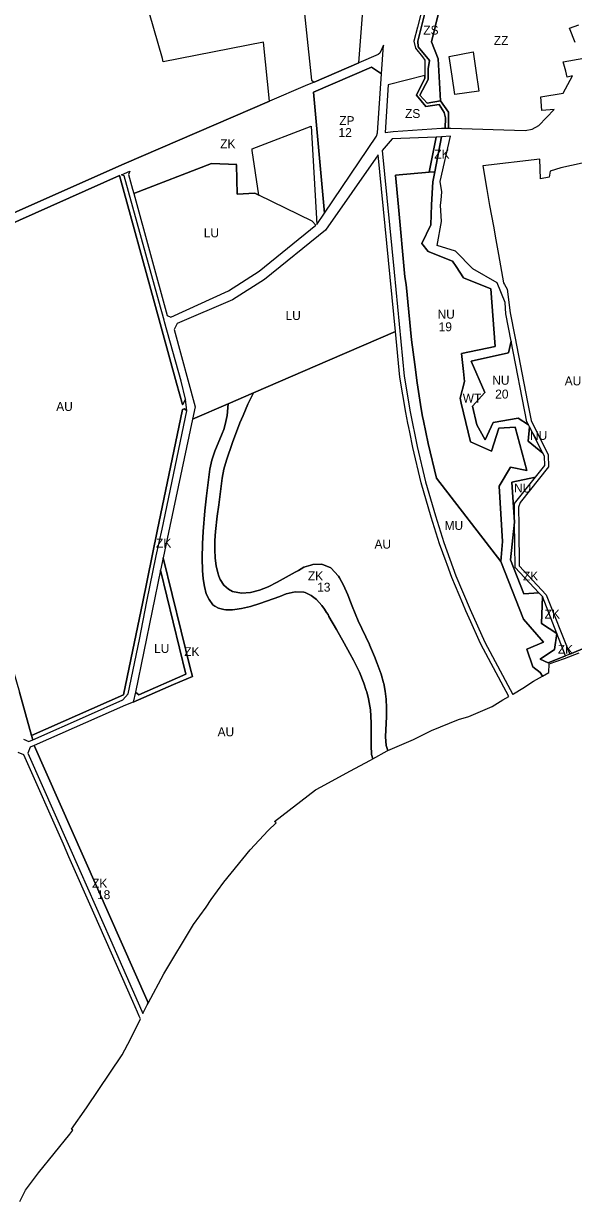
# Model space of a CAD drawing. Extents: x -522079 to -518833, y -1142398 to -1139961.
# Drawn here: x -521003 to -520386, y -1142382 to -1141061 of the extents above; entities that cross this region are included whole.
import ezdxf

# ---------------------------------------------------------------- set-up
doc = ezdxf.new("R2010")
doc.units = 0
for name, color, linetype in [('90640013', 7, 'Continuous'), ('90660013', 7, 'Continuous'), ('90670013', 7, 'Continuous'), ('90680023', 7, 'Continuous'), ('90710013', 7, 'Continuous'), ('90710023', 7, 'Continuous'), ('90730013', 7, 'Continuous'), ('90730023', 7, 'Continuous'), ('90750013', 7, 'Continuous'), ('90770013', 7, 'Continuous'), ('90830013', 7, 'Continuous'), ('ID_navrh', 7, 'Continuous')]:
    doc.layers.add(name, color=color, linetype=linetype)

msp = doc.modelspace()

# ---------------------------------------------------------------- linework, layer by layer
at = {"layer": '90640013'}
for points in [[(-520556.5, -1141046.1), (-520561.24, -1141065.24), (-520565.18, -1141081.15), (-520563.4, -1141088.78), (-520555.74, -1141098.46), (-520552.84, -1141102.13), (-520552.98, -1141119.42), (-520553, -1141122.43), (-520562.26, -1141141.67), (-520551.87, -1141154.33), (-520536.94, -1141152.14), (-520531.44, -1141160.96), (-520529.73, -1141167.05), (-520530.26, -1141178.39), (-520526.48, -1141178.44), (-520526.38, -1141166.45), (-520526.34, -1141160.53), (-520535.5, -1141147.72), (-520550.27, -1141150.4), (-520558.62, -1141141.55), (-520549.21, -1141123.97), (-520549.23, -1141120.44), (-520549.29, -1141112.12), (-520547.68, -1141102.49), (-520560.53, -1141087.18), (-520560.89, -1141080.93), (-520556.84, -1141064.48), (-520552.06, -1141045.13)], [(-520276.36, -1141720.39), (-520390.37, -1141768.15), (-520395.26, -1141770.17), (-520414.86, -1141777.92), (-520423.68, -1141774.01), (-520407.65, -1141762.99), (-520405.02, -1141744.98), (-520422.16, -1141733.79), (-520421.11, -1141703.69), (-520425.12, -1141699.44), (-520442.1, -1141700.42), (-520456.84, -1141662.39), (-520452.43, -1141620.06), (-520455.53, -1141575.25), (-520428.95, -1141569.87), (-520418.4, -1141556.83), (-520419, -1141546.21), (-520420.69, -1141542.88), (-520437.33, -1141529.38), (-520435.68, -1141513.27), (-520436.83, -1141511), (-520448.25, -1141503.52), (-520476.51, -1141508.33), (-520485.33, -1141527.78), (-520494.54, -1141511.04), (-520499.43, -1141490.33), (-520485.81, -1141474.99), (-520501.13, -1141439.65), (-520459.35, -1141430.33), (-520456.11, -1141417.28), (-520462.06, -1141386.7), (-520463.1, -1141373.93), (-520471.76, -1141351.9), (-520499.06, -1141336.21), (-520518.61, -1141316.36), (-520539.2, -1141310.09), (-520534.35, -1141283.17), (-520535.3, -1141264.93), (-520534.84, -1141259.42), (-520534.05, -1141249.88), (-520535.7, -1141238.47), (-520524.27, -1141187.6), (-520534.17, -1141188.18), (-520541.94, -1141227.47), (-520544.19, -1141238.83), (-520545.37, -1141264.63), (-520546.39, -1141287.04), (-520556.25, -1141307.68), (-520549.32, -1141316.76), (-520521.95, -1141327.46), (-520517.94, -1141333.55), (-520509.58, -1141346.13), (-520479.06, -1141358.55), (-520474.23, -1141423.42), (-520512.06, -1141431.3), (-520509.69, -1141451.35), (-520508.38, -1141462.38), (-520513.39, -1141481.08), (-520512.09, -1141486.67), (-520501.99, -1141530.25), (-520478.09, -1141540.57), (-520469.99, -1141514.94), (-520451.9, -1141513.8), (-520438.57, -1141562.32), (-520457.06, -1141558.71), (-520469.63, -1141579.9), (-520465.85, -1141641.84), (-520467.83, -1141664.2), (-520442.29, -1141729.04), (-520420.15, -1141754.6), (-520438.59, -1141762.62), (-520431.99, -1141782.5), (-520423.68, -1141788.92), (-520421.03, -1141792.82), (-520413.91, -1141788.74), (-520413.8, -1141779.11), (-520396.49, -1141772.96), (-520379.93, -1141766.64)]]:
    msp.add_lwpolyline(points, dxfattribs=at)
at = {"layer": '90660013'}
msp.add_lwpolyline([(-520552.06, -1141045.13), (-520556.84, -1141064.48), (-520560.89, -1141080.93), (-520560.53, -1141087.18), (-520547.68, -1141102.49), (-520549.29, -1141112.12), (-520549.23, -1141120.44), (-520549.21, -1141123.97), (-520558.62, -1141141.55), (-520550.27, -1141150.4), (-520535.5, -1141147.72), (-520538.13, -1141100.63), (-520545.68, -1141081.75), (-520537, -1141046.7)], dxfattribs=at)
msp.add_lwpolyline([(-520530.26, -1141178.39), (-520529.73, -1141167.05), (-520531.44, -1141160.96), (-520536.94, -1141152.14), (-520551.87, -1141154.33), (-520562.26, -1141141.67), (-520553, -1141122.43), (-520552.98, -1141119.42), (-520594.25, -1141129.86), (-520597.46, -1141183.55), (-520588.63, -1141182.42), (-520534.49, -1141178.34)], close=True, dxfattribs=at)
at = {"layer": '90670013'}
for points in [[(-520537, -1141046.7), (-520545.68, -1141081.75), (-520538.13, -1141100.63), (-520535.5, -1141147.72), (-520526.34, -1141160.53), (-520526.38, -1141166.45), (-520526.48, -1141178.44), (-520523.78, -1141178.47), (-520440.68, -1141181.04), (-520432.59, -1141179.7), (-520425.27, -1141175.41), (-520408.18, -1141157.48), (-520421.91, -1141158.52), (-520423.06, -1141143.4), (-520397.97, -1141139.24), (-520387.46, -1141120.02), (-520393.3, -1141121.36), (-520395.09, -1141114.42), (-520397.79, -1141103.97), (-520374.68, -1141099.98)], [(-520384.48, -1141082.4), (-520390.79, -1141066.51), (-520380.42, -1141062.83)], [(-520498.69, -1141092.95), (-520495.67, -1141113.78), (-520492.31, -1141136.96), (-520519.42, -1141140.9), (-520522.42, -1141120.25), (-520525.62, -1141098.2), (-520498.69, -1141092.95)]]:
    msp.add_lwpolyline(points, dxfattribs=at)
at = {"layer": '90680023'}
msp.add_lwpolyline([(-520601.54, -1141117.64), (-520612.8, -1141110.04), (-520677.78, -1141138.02), (-520665.65, -1141273.94), (-520607.02, -1141187.64), (-520606.07, -1141183.78)], close=True, dxfattribs=at)
at = {"layer": '90710013'}
msp.add_lwpolyline([(-521140.66, -1141340.91), (-520895.18, -1141231.65), (-520856.02, -1141374.46), (-520831.3, -1141464.59), (-520824.77, -1141488.43), (-520824.28, -1141488.21), (-520821.3, -1141482.16), (-520826.14, -1141462.3), (-520844.73, -1141395.54), (-520845.27, -1141393.64), (-520851.22, -1141372.34), (-520889.86, -1141232.13), (-520893.13, -1141230.74), (-520883.56, -1141226.59), (-520885.33, -1141230.38), (-520880.53, -1141246.97), (-520879.25, -1141251.61), (-520792.12, -1141217.97), (-520763.86, -1141219.18), (-520764.2, -1141219.7), (-520763.26, -1141252.34), (-520743.39, -1141251.48), (-520739.03, -1141253.62), (-520746.38, -1141203.48), (-520746.65, -1141201.66), (-520680.34, -1141176.38), (-520674.18, -1141286.49), (-520665.65, -1141273.94), (-520677.78, -1141138.02), (-520612.8, -1141110.04), (-520601.54, -1141117.64), (-520599.33, -1141085.41), (-520603.47, -1141094.45), (-520605.48, -1141096), (-520627.13, -1141105.32), (-520676.95, -1141126.77), (-520686.99, -1141131.09), (-520727.16, -1141148.38), (-520890.16, -1141218.54), (-520895.96, -1141221.04), (-521038.45, -1141284.46)], dxfattribs=at)
for points in [[(-520540.34, -1141188.43), (-520548.16, -1141227.97), (-520541.94, -1141227.47), (-520534.17, -1141188.18)], [(-520993.82, -1141859.25), (-520992.44, -1141864.11), (-520930.02, -1141836.55), (-520891.63, -1141819.53), (-520885.53, -1141812.75), (-520873.01, -1141751.95), (-520864.49, -1141709.14), (-520854, -1141657.98), (-520847.36, -1141628.04), (-520819.82, -1141495.44), (-520822.47, -1141493.04), (-520824.63, -1141494.01), (-520852.89, -1141630.48), (-520869.65, -1141711.4), (-520878.55, -1141754.38), (-520890.85, -1141813.79)], [(-520425.12, -1141699.44), (-520451.86, -1141671.07), (-520452.43, -1141620.06), (-520456.84, -1141662.39), (-520442.1, -1141700.42)], [(-520877.47, -1141810.66), (-520879.93, -1141822.22), (-520834.71, -1141802.36), (-520813.61, -1141793.09), (-520815.91, -1141783.74), (-520846.32, -1141660.34), (-520849.15, -1141674.02), (-520820.88, -1141790.77), (-520873.57, -1141813.91)], [(-520421.11, -1141703.69), (-520422.16, -1141733.79), (-520405.02, -1141744.98)], [(-520395.26, -1141770.17), (-520405.02, -1141744.98), (-520407.65, -1141762.99), (-520423.68, -1141774.01), (-520414.86, -1141777.92)]]:
    msp.add_lwpolyline(points, close=True, dxfattribs=at)
at = {"layer": '90710023'}
for points in [[(-520594.48, -1141876.16), (-520596.28, -1141870.76), (-520596.94, -1141860.76), (-520596.03, -1141838.3), (-520595.96, -1141828.23), (-520596.37, -1141818.65), (-520597.38, -1141809.66), (-520598.99, -1141801.26), (-520599.21, -1141800.48), (-520601.96, -1141790.76), (-520606.35, -1141778.69), (-520609.24, -1141770.76), (-520614.96, -1141757.69), (-520615.1, -1141757.37), (-520627.89, -1141730.76), (-520634.31, -1141714.34), (-520636.14, -1141709.65), (-520639.3, -1141701.58), (-520644.07, -1141690.76), (-520648.49, -1141682.61), (-520649.78, -1141680.76), (-520658.49, -1141671.54), (-520668.49, -1141667.34), (-520678.49, -1141667.68), (-520680.68, -1141668.57), (-520688.49, -1141670.81), (-520694.77, -1141674.48), (-520698.49, -1141676.14), (-520708.49, -1141681.73), (-520718.49, -1141687.63), (-520728.49, -1141692.76), (-520738.49, -1141696.45), (-520748.49, -1141698.92), (-520758.49, -1141699.72), (-520768.49, -1141697.8), (-520772.97, -1141695.24), (-520778.49, -1141691.03), (-520782.24, -1141684.51), (-520783.84, -1141680.76), (-520784.93, -1141677.21), (-520786.77, -1141669.05), (-520787.95, -1141660.76), (-520788.48, -1141650.77), (-520788.33, -1141640.76), (-520787.54, -1141630.76), (-520785.6, -1141613.65), (-520784.01, -1141600.98), (-520780.2, -1141570.76), (-520778.33, -1141560.76), (-520775.47, -1141550.76), (-520768.6, -1141530.76), (-520760.32, -1141508.93), (-520756.59, -1141500.76), (-520751.33, -1141487.92), (-520748.12, -1141481.13), (-520745.05, -1141475.27), (-520773.3, -1141487.53), (-520774.42, -1141500.76), (-520776.72, -1141510.76), (-520778.49, -1141516.25), (-520780.07, -1141520.76), (-520788.33, -1141540.76), (-520791.87, -1141550.76), (-520794.11, -1141560.76), (-520797.9, -1141590.76), (-520799.43, -1141607.66), (-520801.52, -1141630.76), (-520802.32, -1141644.59), (-520802.58, -1141660.76), (-520802.12, -1141674.39), (-520801.39, -1141683.67), (-520800.15, -1141692.43), (-520798.14, -1141700.76), (-520794.86, -1141707.13), (-520790.51, -1141712.79), (-520788.49, -1141714.55), (-520784.24, -1141716.51), (-520778.49, -1141718.29), (-520776.22, -1141718.49), (-520768.49, -1141718.49), (-520765.89, -1141718.16), (-520758.49, -1141717.01), (-520748.49, -1141714.63), (-520737.83, -1141711.42), (-520715.69, -1141703.56), (-520708.49, -1141700.66), (-520698.49, -1141698.33), (-520688.49, -1141698.8), (-520686.99, -1141699.26), (-520680.23, -1141702.5), (-520674.58, -1141706.85), (-520668.49, -1141713.61), (-520665.44, -1141717.71), (-520663.04, -1141721.47), (-520661.54, -1141723.82), (-520660.44, -1141725.82), (-520652.18, -1141740.76), (-520643.44, -1141755.72), (-520637, -1141767.42), (-520632.79, -1141775.07), (-520626.68, -1141787.7), (-520626.27, -1141788.54), (-520621.34, -1141800.76), (-520618.62, -1141809.07), (-520618.17, -1141810.44), (-520616.14, -1141818.42), (-520614.04, -1141830.76), (-520613.05, -1141845.33), (-520613.19, -1141870.76), (-520612.71, -1141880.76), (-520611.23, -1141885.62), (-520595.23, -1141876.48), (-520594.48, -1141876.16)], [(-521003.04, -1141863.38), (-520997.06, -1141866.15), (-520992.44, -1141864.11), (-520993.82, -1141859.25), (-521007.52, -1141810.87)]]:
    msp.add_lwpolyline(points, dxfattribs=at)
msp.add_lwpolyline([(-520990.8, -1141870.5), (-520995.39, -1141872.52), (-520997.93, -1141879.1), (-520967.25, -1141948.55), (-520939.85, -1142010.61), (-520905.36, -1142088.65), (-520874.16, -1142159.29), (-520870.13, -1142168.42), (-520868.95, -1142171.08), (-520864.2, -1142161.29), (-520863.18, -1142159.4), (-520864.37, -1142156.71)], close=True, dxfattribs=at)
at = {"layer": '90730013'}
for points in [[(-520435.68, -1141513.27), (-520437.33, -1141529.38), (-520420.69, -1141542.88), (-520435.68, -1141513.27)], [(-520428.95, -1141569.87), (-520455.53, -1141575.25), (-520452.43, -1141620.06), (-520452.66, -1141599.19), (-520428.95, -1141569.87)]]:
    msp.add_lwpolyline(points, dxfattribs=at)
at = {"layer": '90730023'}
for points in [[(-520467.83, -1141664.2), (-520465.85, -1141641.84), (-520469.63, -1141579.9), (-520457.06, -1141558.71), (-520438.57, -1141562.32), (-520451.9, -1141513.8), (-520469.99, -1141514.94), (-520478.09, -1141540.57), (-520501.99, -1141530.25), (-520512.09, -1141486.67), (-520513.39, -1141481.08), (-520508.38, -1141462.38), (-520509.69, -1141451.35), (-520512.06, -1141431.3), (-520474.23, -1141423.42), (-520479.06, -1141358.55), (-520509.58, -1141346.13), (-520517.94, -1141333.55), (-520521.95, -1141327.46), (-520549.32, -1141316.76), (-520556.25, -1141307.68), (-520546.39, -1141287.04), (-520545.37, -1141264.63), (-520544.19, -1141238.83), (-520541.94, -1141227.47), (-520548.16, -1141227.97), (-520585.84, -1141231.02), (-520582.4, -1141266.58), (-520575.29, -1141345.21), (-520573.91, -1141353.97), (-520567.96, -1141415.92), (-520564.35, -1141443.41), (-520561.66, -1141463.92), (-520557.24, -1141493.24), (-520555.49, -1141501.75), (-520554.45, -1141506.79), (-520549.23, -1141532.17), (-520539.75, -1141570.9)], [(-520456.11, -1141417.28), (-520459.35, -1141430.33), (-520501.13, -1141439.65), (-520485.81, -1141474.99), (-520499.43, -1141490.33), (-520494.54, -1141511.04), (-520485.33, -1141527.78), (-520476.51, -1141508.33), (-520448.25, -1141503.52), (-520436.83, -1141511), (-520438.53, -1141507.64)]]:
    msp.add_lwpolyline(points, close=True, dxfattribs=at)
at = {"layer": '90750013'}
for points in [[(-520727.16, -1141148.38), (-520733.88, -1141082.24), (-520846.14, -1141104.23), (-520847.24, -1141100.33), (-520861.45, -1141049.84), (-520872.93, -1141009.05), (-520881.52, -1140979.72), (-520885.58, -1140965.84), (-520888.93, -1140954.41), (-520892.3, -1140942.89), (-520959.78, -1140968.46), (-520964.29, -1140970.32), (-521085.77, -1141016.42), (-521111.47, -1141027.75), (-521154.28, -1141046.62), (-521190.59, -1141062.63), (-521216.29, -1141073.97), (-521143.42, -1141331.19), (-521117.38, -1141319.6), (-521081.35, -1141303.56), (-521038.45, -1141284.46), (-520895.96, -1141221.04), (-520890.16, -1141218.54)], [(-520993.82, -1141859.25), (-520890.85, -1141813.79), (-520878.55, -1141754.38), (-520869.65, -1141711.4), (-520852.89, -1141630.48), (-520824.63, -1141494.01), (-520822.47, -1141493.04), (-520819.82, -1141495.44), (-520821.3, -1141482.16), (-520824.28, -1141488.21), (-520824.77, -1141488.43), (-520831.3, -1141464.59), (-520856.02, -1141374.46), (-520895.18, -1141231.65), (-521140.66, -1141340.91), (-521100.48, -1141482.76), (-521074.97, -1141572.8), (-521068.18, -1141596.78), (-521066.79, -1141601.67), (-521035.75, -1141711.23), (-521017.38, -1141776.07), (-521007.52, -1141810.87)], [(-520594.48, -1141876.16), (-520565.76, -1141863.93), (-520545.58, -1141853.73), (-520515.18, -1141841.56), (-520503.7, -1141838.29), (-520477.66, -1141826.82), (-520465.55, -1141819.35), (-520458.87, -1141815.72), (-520490.19, -1141756.96), (-520491.98, -1141752.99), (-520501.37, -1141732.13), (-520506.95, -1141719.75), (-520510.4, -1141711.55), (-520522.71, -1141682.28), (-520528.04, -1141667.68), (-520529.1, -1141664.77), (-520536.49, -1141644.52), (-520545.85, -1141614.67), (-520557.06, -1141576.08), (-520566.58, -1141536.47), (-520569.98, -1141519.36), (-520571.03, -1141514.08), (-520572, -1141509.22), (-520574.39, -1141497.17), (-520580.93, -1141457.51), (-520585.72, -1141406.64), (-520659.49, -1141438.15), (-520745.05, -1141475.27), (-520748.12, -1141481.13), (-520751.33, -1141487.92), (-520756.59, -1141500.76), (-520760.32, -1141508.93), (-520768.6, -1141530.76), (-520775.47, -1141550.76), (-520778.33, -1141560.76), (-520780.2, -1141570.76), (-520784.01, -1141600.98), (-520785.6, -1141613.65), (-520787.54, -1141630.76), (-520788.33, -1141640.76), (-520788.48, -1141650.77), (-520787.95, -1141660.76), (-520786.77, -1141669.05), (-520784.93, -1141677.21), (-520783.84, -1141680.76), (-520782.24, -1141684.51), (-520778.49, -1141691.03), (-520772.97, -1141695.24), (-520768.49, -1141697.8), (-520758.49, -1141699.72), (-520748.49, -1141698.92), (-520738.49, -1141696.45), (-520728.49, -1141692.76), (-520718.49, -1141687.63), (-520708.49, -1141681.73), (-520698.49, -1141676.14), (-520694.77, -1141674.48), (-520688.49, -1141670.81), (-520680.68, -1141668.57), (-520678.49, -1141667.68), (-520668.49, -1141667.34), (-520658.49, -1141671.54), (-520649.78, -1141680.76), (-520648.49, -1141682.61), (-520644.07, -1141690.76), (-520639.3, -1141701.58), (-520636.14, -1141709.65), (-520634.31, -1141714.34), (-520627.89, -1141730.76), (-520615.1, -1141757.37), (-520614.96, -1141757.69), (-520609.24, -1141770.76), (-520606.35, -1141778.69), (-520601.96, -1141790.76), (-520599.21, -1141800.48), (-520598.99, -1141801.26), (-520597.38, -1141809.66), (-520596.37, -1141818.65), (-520595.96, -1141828.23), (-520596.03, -1141838.3), (-520596.94, -1141860.76), (-520596.28, -1141870.76)], [(-520990.8, -1141870.5), (-520864.37, -1142156.71), (-520863.18, -1142159.4), (-520845.48, -1142126.69), (-520812.28, -1142071.49), (-520798.04, -1142051.82), (-520792.36, -1142043.35), (-520778.35, -1142023.99), (-520748.85, -1141987.64), (-520728.5, -1141965.87), (-520719.53, -1141957.2), (-520721.33, -1141955.66), (-520675.72, -1141920.42), (-520669.31, -1141916.94), (-520637.23, -1141899.54), (-520613.84, -1141887.11), (-520611.23, -1141885.62), (-520612.71, -1141880.76), (-520613.19, -1141870.76), (-520613.05, -1141845.33), (-520614.04, -1141830.76), (-520616.14, -1141818.42), (-520618.17, -1141810.44), (-520618.62, -1141809.07), (-520621.34, -1141800.76), (-520626.27, -1141788.54), (-520626.68, -1141787.7), (-520632.79, -1141775.07), (-520637, -1141767.42), (-520643.44, -1141755.72), (-520652.18, -1141740.76), (-520660.44, -1141725.82), (-520661.54, -1141723.82), (-520663.04, -1141721.47), (-520665.44, -1141717.71), (-520668.49, -1141713.61), (-520674.58, -1141706.85), (-520680.23, -1141702.5), (-520686.99, -1141699.26), (-520688.49, -1141698.8), (-520698.49, -1141698.33), (-520708.49, -1141700.66), (-520715.69, -1141703.56), (-520737.83, -1141711.42), (-520748.49, -1141714.63), (-520758.49, -1141717.01), (-520765.89, -1141718.16), (-520768.49, -1141718.49), (-520776.22, -1141718.49), (-520778.49, -1141718.29), (-520784.24, -1141716.51), (-520788.49, -1141714.55), (-520790.51, -1141712.79), (-520794.86, -1141707.13), (-520798.14, -1141700.76), (-520800.15, -1141692.43), (-520801.39, -1141683.67), (-520802.12, -1141674.39), (-520802.58, -1141660.76), (-520802.32, -1141644.59), (-520801.52, -1141630.76), (-520799.43, -1141607.66), (-520797.9, -1141590.76), (-520794.11, -1141560.76), (-520791.87, -1141550.76), (-520788.33, -1141540.76), (-520780.07, -1141520.76), (-520778.49, -1141516.25), (-520776.72, -1141510.76), (-520774.42, -1141500.76), (-520773.3, -1141487.53), (-520813.35, -1141504.9), (-520838.97, -1141624.77), (-520846.32, -1141660.34), (-520815.91, -1141783.74), (-520813.61, -1141793.09), (-520834.71, -1141802.36), (-520879.93, -1141822.22), (-520888.63, -1141825.55)]]:
    msp.add_lwpolyline(points, close=True, dxfattribs=at)
for points in [[(-520352.78, -1141212.63), (-520400.61, -1141222.82), (-520412.54, -1141226.76), (-520413.51, -1141233.43), (-520423.33, -1141235.38), (-520423.9, -1141213.13), (-520488.14, -1141220.84), (-520483.58, -1141247.19), (-520480.37, -1141265.08), (-520476.2, -1141288.34), (-520473.45, -1141303.71), (-520470.52, -1141320.08), (-520464.8, -1141352.03), (-520463.71, -1141353.8), (-520460.62, -1141358.83), (-520457.31, -1141385.57), (-520452.14, -1141412.08), (-520437.82, -1141485.59), (-520433.82, -1141506.13), (-520414.56, -1141544.64), (-520414.26, -1141558.37), (-520446.02, -1141598.19), (-520447.82, -1141603.5), (-520447.63, -1141624.46), (-520447.6, -1141627.85), (-520447.22, -1141669.1), (-520417.08, -1141701.53), (-520390.37, -1141768.15), (-520276.36, -1141720.39)], [(-521007.1, -1142381.81), (-521000.81, -1142369.28), (-520986.1, -1142349.82), (-520951.1, -1142306.31), (-520948.83, -1142303.49), (-520947.69, -1142302.08), (-520949.04, -1142300.8), (-520932.3, -1142276.81), (-520892.25, -1142217.33), (-520882.99, -1142199.96), (-520872.25, -1142177.87), (-520871.84, -1142177.03), (-520873.11, -1142174.16), (-520875.14, -1142169.56), (-520880.4, -1142157.63), (-520924.06, -1142058.74), (-520951.97, -1141995.53), (-520958.2, -1141981.43), (-521002.46, -1141881.16), (-521009, -1141878.54)]]:
    msp.add_lwpolyline(points, dxfattribs=at)
at = {"layer": '90770013'}
for points in [[(-520675.31, -1141287.41), (-520679.28, -1141282.96), (-520739.03, -1141253.62), (-520743.39, -1141251.48), (-520763.26, -1141252.34), (-520764.2, -1141219.7), (-520763.86, -1141219.18), (-520792.12, -1141217.97), (-520879.25, -1141251.61), (-520841.7, -1141388.53), (-520837.57, -1141390.54), (-520773.04, -1141360.9), (-520738.6, -1141338.95), (-520675.31, -1141287.41)], [(-520773.3, -1141487.53), (-520745.05, -1141475.27), (-520659.49, -1141438.15), (-520585.72, -1141406.64), (-520605.35, -1141208.42), (-520664.52, -1141292.81), (-520732.72, -1141348.25), (-520768.7, -1141371.01), (-520830.45, -1141397.51), (-520834.09, -1141404.31), (-520810.51, -1141490.93), (-520813.35, -1141504.9), (-520773.3, -1141487.53)], [(-520877.47, -1141810.66), (-520873.57, -1141813.91), (-520820.88, -1141790.77), (-520849.15, -1141674.02), (-520877.47, -1141810.66)]]:
    msp.add_lwpolyline(points, dxfattribs=at)
at = {"layer": '90830013'}
msp.add_lwpolyline([(-520649.51, -1140960.76), (-520660.47, -1140930.63), (-520699.09, -1140943.92), (-520679.92, -1141124.76), (-520676.95, -1141126.77), (-520627.13, -1141105.32), (-520620.51, -1141022.34), (-520648.03, -1140963.9), (-520649.51, -1140960.76)], dxfattribs=at)
msp.add_lwpolyline([(-520540.34, -1141188.43), (-520589.77, -1141190.43), (-520600.66, -1141203.4), (-520587.35, -1141340.09), (-520576, -1141456.7), (-520569.46, -1141496.36), (-520561.68, -1141535.49), (-520552.2, -1141574.91), (-520541.05, -1141613.27), (-520531.72, -1141643.02), (-520518.1, -1141680.34), (-520502.23, -1141718.09), (-520485.78, -1141754.61), (-520454.47, -1141813.35), (-520453.46, -1141812.83), (-520443.29, -1141806.35), (-520431, -1141798.52), (-520421.03, -1141792.82), (-520423.68, -1141788.92), (-520431.99, -1141782.5), (-520438.59, -1141762.62), (-520420.15, -1141754.6), (-520442.29, -1141729.04), (-520467.83, -1141664.2), (-520539.75, -1141570.9), (-520549.23, -1141532.17), (-520554.45, -1141506.79), (-520555.49, -1141501.75), (-520557.24, -1141493.24), (-520561.66, -1141463.92), (-520564.35, -1141443.41), (-520567.96, -1141415.92), (-520573.91, -1141353.97), (-520575.29, -1141345.21), (-520582.4, -1141266.58), (-520585.84, -1141231.02), (-520548.16, -1141227.97)], close=True, dxfattribs=at)

# ---------------------------------------------------------------- texts
at = {"layer": '90640013'}
msp.add_text('WT', height=10, rotation=0, dxfattribs=at).set_placement((-520510.5, -1141486.11))
at = {"layer": '90660013'}
for rotation, p in [(360, (-520554.7, -1141073.6)), (0, (-520575.15, -1141167.12))]:
    msp.add_text('ZS', height=10, rotation=rotation, dxfattribs=at).set_placement(p)
at = {"layer": '90670013'}
msp.add_text('ZZ', height=10, rotation=360, dxfattribs=at).set_placement((-520475.63, -1141085.14))
at = {"layer": '90680023'}
msp.add_text('ZP', height=10, rotation=360, dxfattribs=at).set_placement((-520648.93, -1141175.04))
at = {"layer": '90710013'}
for rotation, p in [(0, (-520782.37, -1141200.99)), (360, (-520542.41, -1141212.58)), (0, (-520854.29, -1141648.73)), (0, (-520443.04, -1141685.63)), (0, (-520418.66, -1141728.25)), (0, (-520403.92, -1141767.78)), (0, (-520822.71, -1141770.4))]:
    msp.add_text('ZK', height=10, rotation=rotation, dxfattribs=at).set_placement(p)
at = {"layer": '90710023'}
msp.add_text('ZK', height=10, rotation=0, dxfattribs=at).set_placement((-520684.09, -1141685.53))
msp.add_text('ZK', height=10, dxfattribs=at).set_placement((-520925.96, -1142030.09))
at = {"layer": '90730013'}
for rotation, p in [(360, (-520435.14, -1141527.95)), (0, (-520453.07, -1141586.95))]:
    msp.add_text('NU', height=10, rotation=rotation, dxfattribs=at).set_placement(p)
at = {"layer": '90730023'}
for p in [(-520538.73, -1141392.07), (-520477.46, -1141466.17)]:
    msp.add_text('NU', height=10, rotation=360, dxfattribs=at).set_placement(p)
at = {"layer": '90750013'}
for rotation, p in [(0, (-520396.22, -1141466.89)), (360, (-520966.2, -1141495.53)), (360, (-520609.42, -1141649.93)), (360, (-520785.3, -1141860.35))]:
    msp.add_text('AU', height=10, rotation=rotation, dxfattribs=at).set_placement(p)
at = {"layer": '90770013'}
for rotation, p in [(360, (-520800.76, -1141300.92)), (360, (-520709.11, -1141393.55)), (0, (-520856.48, -1141766.8))]:
    msp.add_text('LU', height=10, rotation=rotation, dxfattribs=at).set_placement(p)
at = {"layer": '90830013'}
msp.add_text('MU', height=10, rotation=0, dxfattribs=at).set_placement((-520530.85, -1141628.93))
at = {"layer": 'ID_navrh'}
for s, rotation, p in [('12', 360, (-520649.77, -1141188.43)), ('19', 360, (-520537.47, -1141406.19)), ('20', 360, (-520474.09, -1141481.63)), ('13', 360, (-520673.67, -1141698.12)), ('18', 0, (-520920.46, -1142042.9))]:
    msp.add_text(s, height=10, rotation=rotation, dxfattribs=at).set_placement(p)

doc.saveas('drawing.dxf')
